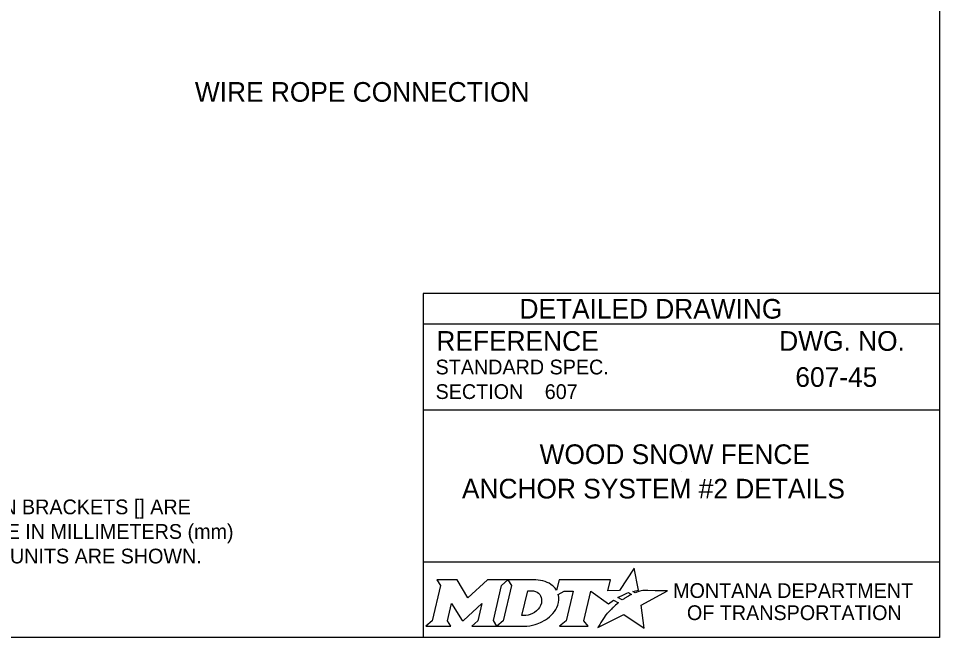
# Model space of a CAD drawing. Extents: x 49991.4 to 50021, y 49987.6 to 50011.4.
# Drawn here: x 50013.004 to 50016.75, y 49987.799 to 49990.318 of the extents above; entities that cross this region are included whole.
import ezdxf

# ---------------------------------------------------------------- set-up
doc = ezdxf.new("R2010")
doc.units = 0
for name, color, linetype in [('Default', 7, 'Continuous'), ('Level 1', 7, 'Continuous'), ('Level 2', 7, 'Continuous'), ('Level 5', 7, 'Continuous')]:
    doc.layers.add(name, color=color, linetype=linetype)

msp = doc.modelspace()

# ---------------------------------------------------------------- linework, layer by layer
at = {"layer": 'Default'}
for points in [[(50015.5126, 49987.9811), (50015.5023, 49987.9867), (50015.5139, 49987.9895), (50015.5255, 49987.9915), (50015.5081, 49988.0816), (50015.4486, 49987.9903), (50015.4013, 49987.9896), (50015.4116, 49988.0337), (50015.2024, 49988.0338), (50015.1923, 49987.9913), (50015.1865, 49987.9996)], [(50014.7056, 49988.0338), (50014.7197, 49988.0104), (50014.6862, 49987.8671), (50014.6605, 49987.8446), (50014.7621, 49987.8446), (50014.7486, 49987.8674), (50014.7648, 49987.9375), (50014.8085, 49987.8685), (50014.8138, 49987.8685), (50014.8889, 49987.938), (50014.8725, 49987.8669), (50014.8478, 49987.8449), (50014.9494, 49987.8449), (50014.9356, 49987.8682), (50014.9688, 49988.0106)], [(50014.9688, 49988.0106), (50014.9941, 49988.0338), (50014.9117, 49988.0338), (50014.8321, 49987.9608), (50014.7876, 49988.0335), (50014.7056, 49988.0338)], [(50015.1077, 49988.0338), (50014.9941, 49988.0338), (50015.0088, 49988.0109), (50014.9749, 49987.8671), (50014.9494, 49987.8449), (50015.06, 49987.8449)], [(50015.1317, 49987.9471), (50015.1305, 49987.939), (50015.1273, 49987.9297), (50015.1231, 49987.9215), (50015.1175, 49987.914), (50015.111, 49987.9071), (50015.1031, 49987.9008), (50015.0948, 49987.8961), (50015.0857, 49987.8922), (50015.0766, 49987.8899), (50015.0674, 49987.889), (50015.0515, 49987.889), (50015.0751, 49987.989), (50015.0911, 49987.989), (50015.0987, 49987.9884), (50015.1063, 49987.9865), (50015.1129, 49987.9835), (50015.119, 49987.9793), (50015.1238, 49987.9743), (50015.1275, 49987.9683), (50015.1302, 49987.9621), (50015.1318, 49987.9547), (50015.1318, 49987.9517), (50015.1317, 49987.9471)], [(50015.1991, 49987.9747), (50015.2237, 49987.9878), (50015.2606, 49987.9878), (50015.232, 49987.8673), (50015.2045, 49987.8446), (50015.3207, 49987.8446), (50015.3037, 49987.8675), (50015.3319, 49987.9877), (50015.4032, 49987.936), (50015.4243, 49987.9511), (50015.444, 49987.9402)], [(50015.3882, 49987.8843), (50015.3729, 49987.8599), (50015.3682, 49987.8524), (50015.3624, 49987.8438), (50015.3601, 49987.8395), (50015.4654, 49987.8926), (50015.5493, 49987.8375), (50015.5362, 49987.9302), (50015.6431, 49987.9886), (50015.5938, 49987.9894), (50015.5637, 49987.9898), (50015.5429, 49987.9901), (50015.5361, 49987.9886), (50015.5312, 49987.9874), (50015.5228, 49987.9851), (50015.5126, 49987.9811)], [(50015.4622, 49987.9535), (50015.4598, 49987.9518), (50015.4415, 49987.9614), (50015.4518, 49987.9671), (50015.4559, 49987.9693), (50015.4645, 49987.9733), (50015.4702, 49987.9759), (50015.4781, 49987.9789), (50015.4854, 49987.9816), (50015.4972, 49987.9742), (50015.4932, 49987.9721), (50015.4886, 49987.9696), (50015.4844, 49987.9674), (50015.4794, 49987.9645), (50015.4775, 49987.9634), (50015.4748, 49987.9618), (50015.4723, 49987.9604), (50015.47, 49987.9588), (50015.4674, 49987.957), (50015.4647, 49987.9552), (50015.4622, 49987.9535)], [(50015.4021, 49987.9004), (50015.4021, 49987.9004)], [(50015.1057, 49987.8522), (50015.1141, 49987.8548), (50015.1271, 49987.8602), (50015.1475, 49987.8712)]]:
    msp.add_lwpolyline(points, dxfattribs=at)
for centre, radius, start, end in [((50015.1308, 49987.9554), 0.0709, 339.5329, 15.8582), ((50015.0868, 49987.9727), 0.1183, 300.9103, 339.1383)]:
    msp.add_arc(centre, radius, start, end, dxfattribs=at)
for centre, major_axis, ratio, start_param, end_param in [((50015.1056, 49987.9864), (0.0834, -0.0037), 0.568097, 0.61298, 1.570796), ((50015.1612, 49987.9937), (0.0361, -0.0295), 0.469099, 1.225588, 1.570796), ((50015.4329, 49987.9305), (-0.0112, -0.0097), 0.021651, 3.157348, 6.283185), ((50015.3952, 49987.8923), (-0.00694, -0.00806), 0.008222, 0, 3.137361), ((50015.4119, 49987.9106), (-0.0098, -0.0102), 0.016458, 3.141593, 6.279097), ((50015.0603, 49987.9932), (0, 0.1484), 0.987302, 3.139398, 3.456847)]:
    msp.add_ellipse(centre, major_axis=major_axis, ratio=ratio, start_param=start_param, end_param=end_param, dxfattribs=at)
at = {"layer": 'Level 1'}
msp.add_lwpolyline([(49999.3835, 49998.9992), (50016.7501, 49998.9992), (50016.7501, 49987.7988), (49999.3835, 49987.7988)], close=True, dxfattribs=at)
at = {"layer": 'Level 5'}
for p, q in [((50016.7501, 49989.1988), (50014.6501, 49989.1988)), ((50014.6501, 49989.1988), (50014.6501, 49987.7988)), ((50016.7501, 49989.0738), (50014.6501, 49989.0738)), ((50016.3862, 49988.8587), (50016.3862, 49988.8587)), ((50015.1444, 49988.7993), (50015.1444, 49988.7993)), ((50016.7501, 49988.7238), (50014.6501, 49988.7238)), ((50015.7001, 49988.4747), (50015.7001, 49988.4747)), ((50016.7501, 49988.1057), (50014.6501, 49988.1057))]:
    msp.add_line(p, q, dxfattribs=at)

# ---------------------------------------------------------------- texts
at = {"layer": 'Default'}
for s, p in [('MONTANA DEPARTMENT', (50015.6663, 49987.96)), ('OF TRANSPORTATION', (50015.7225, 49987.87))]:
    msp.add_text(s, height=0.06, dxfattribs=at).set_placement(p)
at = {"layer": 'Level 2'}
for s, height, p in [('WIRE ROPE CONNECTION', 0.08, (50013.7215, 49989.9785)), ('607-45', 0.08, (50016.1636, 49988.8187)), ('607', 0.06, (50015.1444, 49988.7693)), (' WOOD SNOW FENCE', 0.08, (50015.0937, 49988.5047)), ('ANCHOR SYSTEM #2 DETAILS', 0.08, (50014.8076, 49988.3647)), ('UNITS SHOWN IN BRACKETS [] ARE ', 0.06, (50012.3229, 49988.3004)), ('METRIC AND ARE IN MILLIMETERS (mm) ', 0.06, (50012.3229, 49988.2004)), ('UNLESS OTHER UNITS ARE SHOWN.', 0.06, (50012.3229, 49988.1004))]:
    msp.add_text(s, height=height, dxfattribs=at).set_placement(p)
at = {"layer": 'Level 5'}
for s, height, p in [('DETAILED DRAWING', 0.0799, (50015.0418, 49989.0963)), ('REFERENCE', 0.08, (50014.7037, 49988.9654)), ('DWG. NO.', 0.08, (50016.0979, 49988.9654)), ('STANDARD SPEC.', 0.06, (50014.7004, 49988.8694)), ('SECTION', 0.06, (50014.7004, 49988.7694))]:
    msp.add_text(s, height=height, dxfattribs=at).set_placement(p)

doc.saveas('drawing.dxf')
